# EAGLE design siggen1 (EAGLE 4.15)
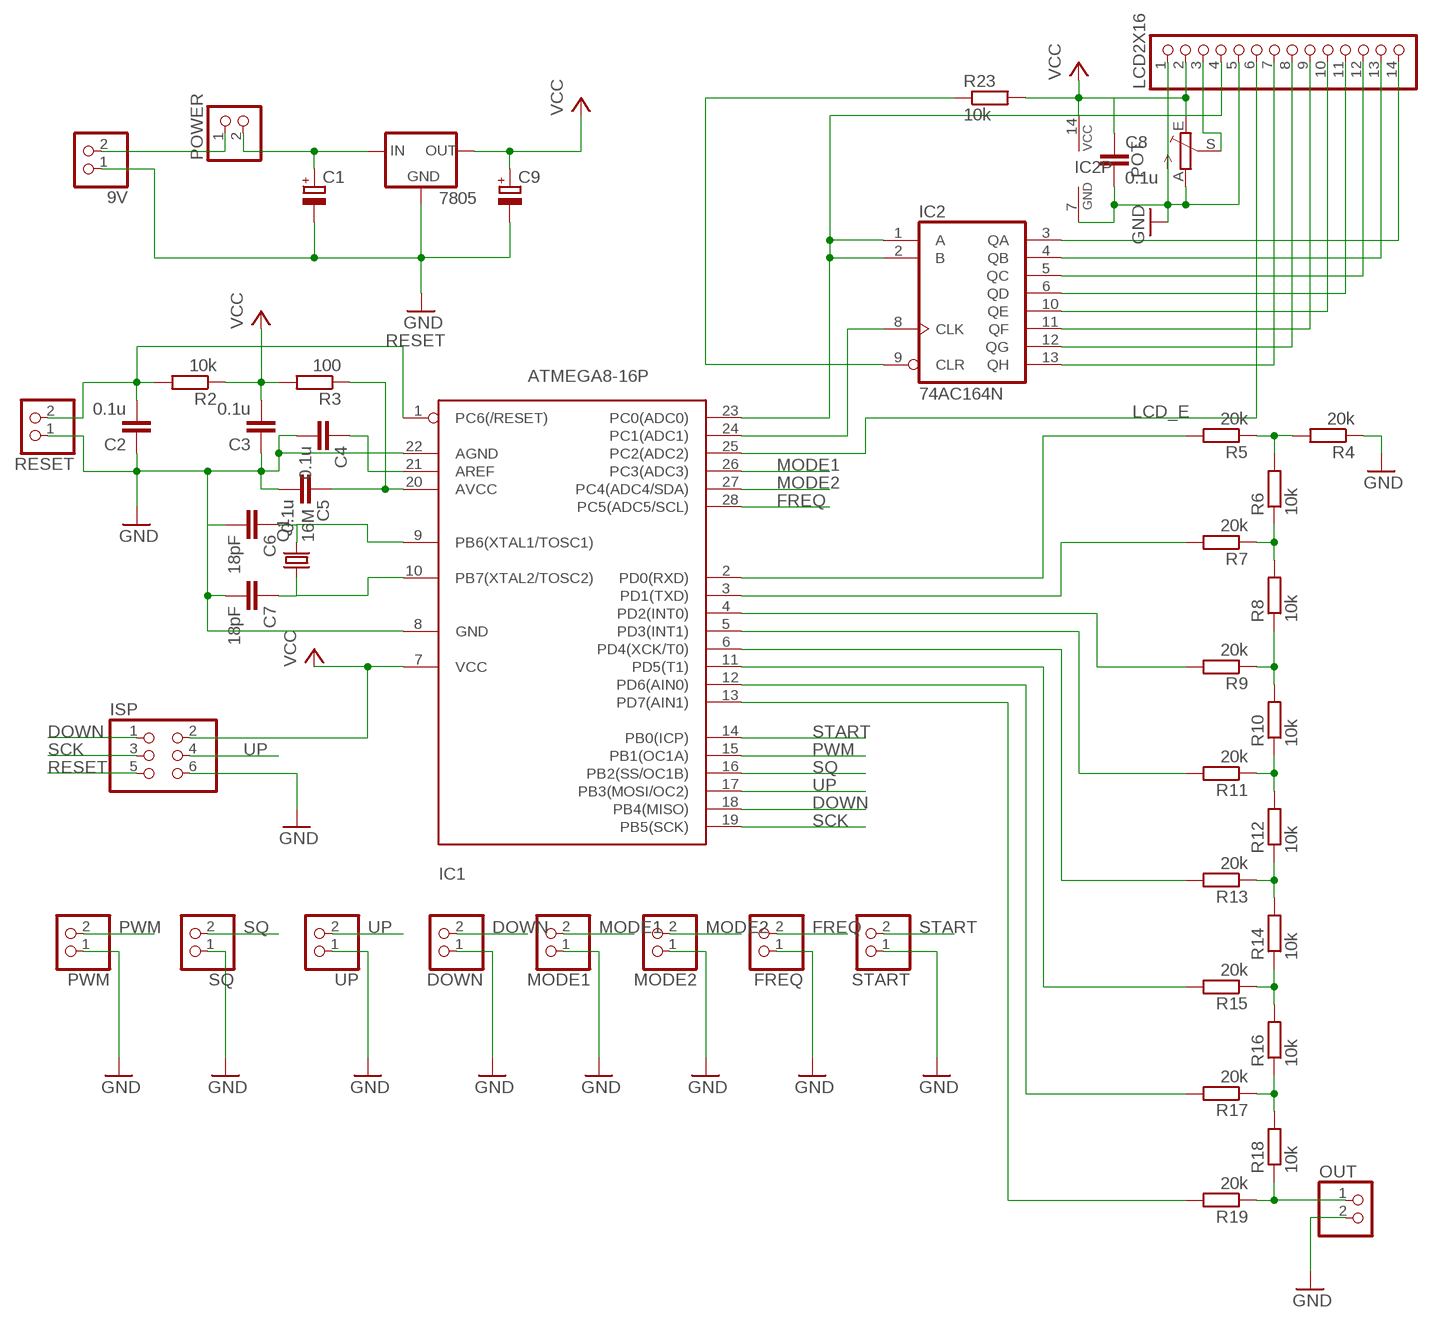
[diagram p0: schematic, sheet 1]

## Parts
9V  PINHD-1X2  [1X02]
7805  78MXXL  [78MXXL]
C1  CPOL-EUE5-4  [E5-4]
C2  0.1u  C-EUC0805  [C0805]
C3  0.1u  C-EUC0805  [C0805]
C4  0.1u  C-EUC0805  [C0805]
C5  0.1u  C-EUC0805  [C0805]
C6  18pF  C-EUC0805  [C0805]
C7  18pF  C-EUC0805  [C0805]
C8  0.1u  C-EUC0805  [C0805]
C9  CPOL-EUE5-4  [E5-4]
DOWN  PINHD-1X2  [1X02]
FREQ  PINHD-1X2  [1X02]
IC1  ATMEGA8-16P  [DIL28-3]
IC2  74AC164N  [DIL14]
ISP  PINHD-2X3  [2X03]
LCD2X16  PINHD-1X14  [1X14]
MODE1  PINHD-1X2  [1X02]
MODE2  PINHD-1X2  [1X02]
OUT  PINHD-1X2  [1X02]
POT  TRIM_EU-B64W  [B64W]
POWER  PINHD-1X2  [1X02]
PWM  PINHD-1X2  [1X02]
Q1  16M  CRYTALHC49S  [HC49/S]
R2  10k  R-EU_V526-0  [V526-0]
R3  100  R-EU_M0805  [M0805]
R4  20k  R-EU_M0805  [M0805]
R5  20k  R-EU_M0805  [M0805]
R6  10k  R-EU_M0805  [M0805]
R7  20k  R-EU_M0805  [M0805]
R8  10k  R-EU_M0805  [M0805]
R9  20k  R-EU_M0805  [M0805]
R10  10k  R-EU_M0805  [M0805]
R11  20k  R-EU_M0805  [M0805]
R12  10k  R-EU_M0805  [M0805]
R13  20k  R-EU_M0805  [M0805]
R14  10k  R-EU_M0805  [M0805]
R15  20k  R-EU_M0805  [M0805]
R16  10k  R-EU_M0805  [M0805]
R17  20k  R-EU_M0805  [M0805]
R18  10k  R-EU_M0805  [M0805]
R19  20k  R-EU_M0805  [M0805]
R23  10k  R-EU_M0805  [M0805]
RESET  PINHD-1X2  [1X02]
SQ  PINHD-1X2  [1X02]
START  PINHD-1X2  [1X02]
UP  PINHD-1X2  [1X02]

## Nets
DOWN: DOWN.2 IC1.18(PB4(MISO)) ISP.1
FREQ: FREQ.2 IC1.28(PC5(ADC5/SCL))
GND: 9V.1 7805.GND C1.- C2.1 C3.1 C4.2 C5.2 C6.2 C7.2 C8.2 C9.- DOWN.1 FREQ.1 IC1.8(GND) IC1.22(AGND) IC2.7(GND) ISP.6 LCD2X16.1 LCD2X16.5 MODE1.1 MODE2.1 OUT.2 POT.A PWM.1 R4.1 RESET.1 SQ.1 START.1 UP.1
LCD_E: IC1.25(PC2(ADC2)) LCD2X16.6
MODE1: IC1.26(PC3(ADC3)) MODE1.2
MODE2: IC1.27(PC4(ADC4/SDA)) MODE2.2
N$1: 7805.IN C1.+ POWER.2
N$2: C4.1 IC1.21(AREF)
N$3: C6.1 IC1.9(PB6(XTAL1/TOSC1)) Q1.2
N$4: C7.1 IC1.10(PB7(XTAL2/TOSC2)) Q1.1
N$5: LCD2X16.3 POT.S
N$6: IC2.3(QA) LCD2X16.14
N$7: IC2.4(QB) LCD2X16.13
N$8: IC2.5(QC) LCD2X16.12
N$9: C5.1 IC1.20(AVCC) R3.1
N$10: IC2.6(QD) LCD2X16.11
N$11: IC2.10(QE) LCD2X16.10
N$12: IC2.11(QF) LCD2X16.9
N$13: IC2.12(QG) LCD2X16.8
N$14: IC2.13(QH) LCD2X16.7
N$15: R4.2 R5.1 R6.2
N$16: IC2.9(CLR) R23.1
N$17: IC1.23(PC0(ADC0)) IC2.1(A) IC2.2(B) LCD2X16.4
N$18: R6.1 R7.1 R8.2
N$19: IC1.24(PC1(ADC1)) IC2.8(CLK)
N$20: R8.1 R9.1 R10.2
N$21: R10.1 R11.1 R12.2
N$22: R12.1 R13.1 R14.2
N$23: R14.1 R15.1 R16.2
N$24: R16.1 R17.1 R18.2
N$25: OUT.1 R18.1 R19.1
N$26: 9V.2 POWER.1
N$27: IC1.2(PD0(RXD)) R5.2
N$28: IC1.3(PD1(TXD)) R7.2
N$29: IC1.4(PD2(INT0)) R9.2
N$30: IC1.5(PD3(INT1)) R11.2
N$31: IC1.6(PD4(XCK/T0)) R13.2
N$32: IC1.11(PD5(T1)) R15.2
N$33: IC1.12(PD6(AIN0)) R17.2
N$34: IC1.13(PD7(AIN1)) R19.2
PWM: IC1.15(PB1(OC1A)) PWM.2
RESET: C2.2 IC1.1(PC6(/RESET)) ISP.5 R2.2 RESET.2
SCK: IC1.19(PB5(SCK)) ISP.3
SQ: IC1.16(PB2(SS/OC1B)) SQ.2
START: IC1.14(PB0(ICP)) START.2
UP: IC1.17(PB3(MOSI/OC2)) ISP.4 UP.2
VCC: 7805.OUT C3.2 C8.1 C9.+ IC1.7(VCC) IC2.14(VCC) ISP.2 LCD2X16.2 POT.E R2.1 R3.2 R23.2

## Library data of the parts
9V DOWN FREQ MODE1 MODE2 OUT POWER PWM RESET SQ START UP = pinhead:PINHD-1X2: PIN HEADER
7805 = v-reg:78MXXL: VOLTAGE REGULATOR
C1 C9 = rcl:CPOL-EU: POLARIZED CAPACITOR, European symbol
C2-C8 = rcl:C-EU: CAPACITOR, European symbol
IC1 = avr:ATMEGA8*P: MICROCONTROLLER 8 Kbytes FLASH 1 kbytes SRAM 512 bytes EEPROM USART 4-channel 10 bit ADC 2-channel 8 bit ADC
IC2 = 74xx-eu:74*164: 8-bit parallel out SHIFT REGISTER
ISP = pinhead:PINHD-2X3: PIN HEADER
LCD2X16 = pinhead:PINHD-1X14: PIN HEADER
POT = pot:TRIM_EU-: POTENTIOMETER
Q1 = crystal:CRYTAL: CRYSTAL
R2-R19 R23 = rcl:R-EU_: RESISTOR, European symbol

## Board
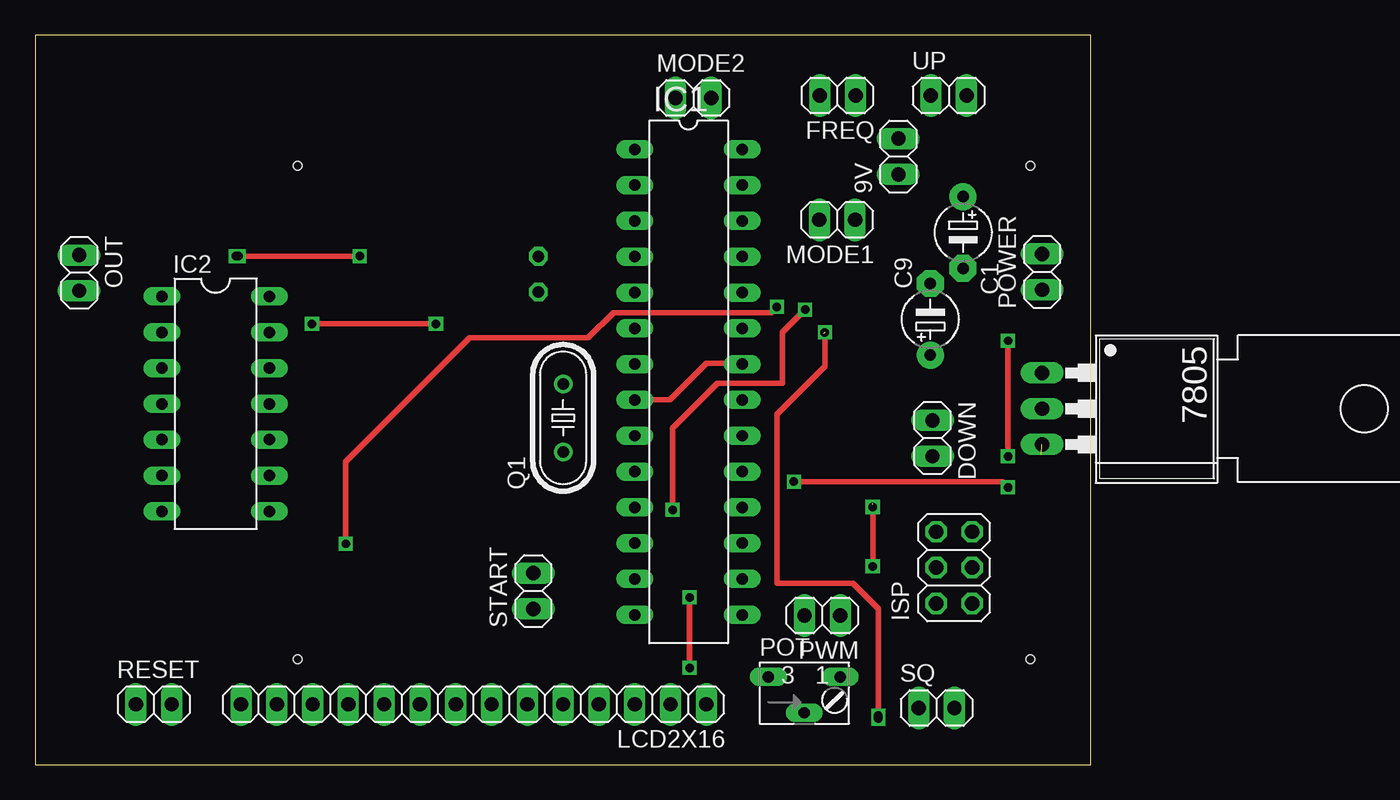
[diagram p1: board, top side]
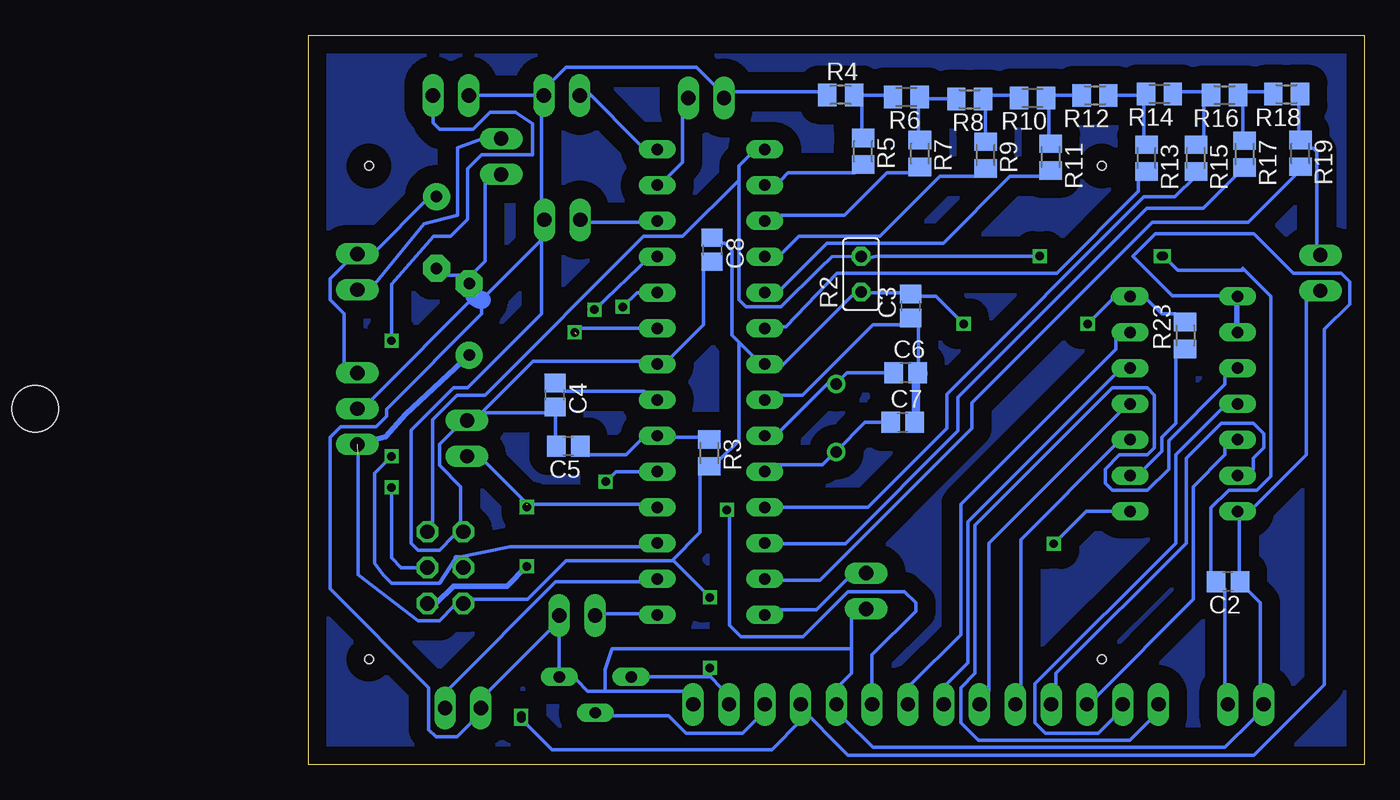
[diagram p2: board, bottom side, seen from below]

Size 74.91 x 51.74 mm. Coordinates in mm from the lower left corner, seen from the top.
Outline: 0,0 74.91,0 74.91,51.74 0,51.74 0,0
Copper layers (1*16): Top 0.035mm / dielectric 1.5mm / Bottom 0.035mm
Design rules "default": minimum track width 10mil, minimum drill 24mil, track to track 8mil, track to pad 8mil, pad to pad 8mil, via to via 8mil, smd to smd 8mil, copper to edge 40mil, drill to drill 8mil, minimum pad ring 10mil, minimum via ring 8mil, stop-mask expansion 4mil, vias tented up to drill 0mil, thermal gap 10mil
Holes 0.6 mm at 18.63,7.47 70.63,7.47 18.63,42.47 70.63,42.47

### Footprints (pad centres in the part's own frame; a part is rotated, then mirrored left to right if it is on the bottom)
1X02 = drill 1.016 long: 1 -1.27,0; 2 1.27,0
78MXXL = drill 1.016 long: GND 0,-5.08; IN -2.54,-5.08; OUT 2.54,-5.08 | hole 3.302: 0,17.78
E5-4 = drill 0.813 pad 1.905 round: + -2.54,0 | drill 0.813 pad 1.905 octagon: - 2.54,0
C0805 = smd 1.3 x 1.5: 1 -0.85,0; 2 0.85,0
DIL28-3 = drill 0.813 long: 1 -16.51,-3.81; 2 -13.97,-3.81; 3 -11.43,-3.81; 4 -8.89,-3.81; 5 -6.35,-3.81; 6 -3.81,-3.81; 7 -1.27,-3.81; 8 1.27,-3.81; 9 3.81,-3.81; 10 6.35,-3.81; 11 8.89,-3.81; 12 11.43,-3.81; 13 13.97,-3.81; 14 16.51,-3.81; 15 16.51,3.81; 16 13.97,3.81; 17 11.43,3.81; 18 8.89,3.81; 19 6.35,3.81; 20 3.81,3.81; 21 1.27,3.81; 22 -1.27,3.81; 23 -3.81,3.81; 24 -6.35,3.81; 25 -8.89,3.81; 26 -11.43,3.81; 27 -13.97,3.81; 28 -16.51,3.81
DIL14 = drill 0.813 long: 1 -7.62,-3.81; 2 -5.08,-3.81; 3 -2.54,-3.81; 4 0,-3.81; 5 2.54,-3.81; 6 5.08,-3.81; 7 7.62,-3.81; 8 7.62,3.81; 9 5.08,3.81; 10 2.54,3.81; 11 0,3.81; 12 -2.54,3.81; 13 -5.08,3.81; 14 -7.62,3.81
2X03 = drill 1.016 octagon: 1 -2.54,-1.27; 2 -2.54,1.27; 3 0,-1.27; 4 0,1.27; 5 2.54,-1.27; 6 2.54,1.27
1X14 = drill 1.016 long: 1 -16.51,0; 2 -13.97,0; 3 -11.43,0; 4 -8.89,0; 5 -6.35,0; 6 -3.81,0; 7 -1.27,0; 8 1.27,0; 9 3.81,0; 10 6.35,0; 11 8.89,0; 12 11.43,0; 13 13.97,0; 14 16.51,0
B64W = drill 0.813 long: A 2.54,0; E -2.54,0; S 0,-2.54
HC49/S = drill 0.813 round: 1 -2.413,0; 2 2.413,0
V526-0 = drill 0.813 octagon: 1 -1.27,0; 2 1.27,0
M0805 = smd 1.3 x 1.6: 1 -0.95,0; 2 0.95,0

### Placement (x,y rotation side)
9V  61.25,43.14 90 top
7805  76.53,25.25 270 top
C1  65.84,37.75 270 top
C2  9.67,12.98 180 bottom
C3  32.19,32.53 90 bottom
C4  57.43,26.22 270 bottom
C5  56.48,22.59 180 bottom
C6  32.55,27.8 0 bottom
C7  32.75,24.28 0 bottom
C8  46.28,36.52 270 bottom
C9  63.52,31.59 90 top
DOWN  63.67,23.15 270 top
FREQ  56.94,47.46 180 top
IC1  46.35,27.14 270 top
IC2  12.8,25.59 270 top
ISP  65.21,13.98 90 top
LCD2X16  31.11,4.28 180 top
MODE1  56.91,38.65 180 top
MODE2  46.7,47.29 0 top
OUT  3.12,34.88 270 top
POT  54.57,6.22 0 top
POWER  71.45,34.96 90 top
PWM  55.86,10.58 180 top
Q1  37.46,24.6 90 top
R2  35.71,34.79 90 bottom
R3  46.47,22.12 270 bottom
R4  37.15,47.51 0 bottom
R5  35.57,43.51 270 bottom
R6  32.5,47.37 180 bottom
R7  31.53,43.35 270 bottom
R8  27.99,47.21 180 bottom
R9  26.87,43.23 270 bottom
R10  23.53,47.3 180 bottom
R11  22.25,43.09 270 bottom
R12  19.11,47.48 180 bottom
R13  15.45,43.02 270 bottom
R14  14.53,47.58 180 bottom
R15  11.95,43.02 270 bottom
R16  9.91,47.5 180 bottom
R17  8.49,43.3 270 bottom
R18  5.5,47.56 180 bottom
R19  4.53,43.36 270 bottom
R23  12.7,30.44 90 bottom
RESET  8.41,4.28 0 top
SQ  63.96,4.02 0 top
START  35.34,12.32 90 top
UP  64.82,47.46 0 top

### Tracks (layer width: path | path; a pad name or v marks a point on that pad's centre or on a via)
DOWN  (via drill 0.6)  (1 unrouted)
  Top 0.406: v59.43,14.07 59.43,18.47
  Bottom 0.254: IC1.18 51.38,18.47 59.38,18.47 62.38,21.47 DOWN.2
  Bottom 0.406: ISP.1 65.86,11.44 64.63,12.67 60.83,12.67 v59.43,14.07
FREQ
  Bottom 0.254: IC1.28 51.38,43.97 55.13,47.72 FREQ.2
GND
  Top 0.406: IC1.8 45.03,25.87 47.63,28.47 50.23,28.47 IC1.22
  Bottom 0.254: R4.1 38.63,47.72 44.88,47.72 MODE2.1 46.13,48.22 47.38,49.47 56.63,49.47 57.63,48.47 FREQ.1 | FREQ.1 58.38,45.97 58.38,39.97 MODE1.1 58.38,37.22 | UP.1 62.88,47.47 58.88,47.47 FREQ.1 | C8.2 46.88,35.22 46.88,31.22 49.13,28.97 IC1.22 51.38,28.62 58.98,28.62 62.63,24.97 | C5.2 57.38,21.97 57.38,24.97 C4.2 58.13,24.97 62.63,24.97 | 62.63,24.97 DOWN.1 64.63,23.72 65.63,22.72 65.63,21.22 64.13,19.72 64.13,17.22 ISP.6 64.63,16.22 65.63,15.22 67.13,15.22 67.63,15.72 67.63,23.72 64.63,26.72 63.63,26.72 58.38,31.97 58.38,37.22 | OUT.2 4.13,32.97 4.13,21.97 7.88,18.22 IC2.7 8.88,17.47 8.88,13.72 C2.1 8.38,12.47 7.38,11.47 7.38,5.72 RESET.1 7.88,3.22 9.88,1.22 34.88,1.22 36.88,3.22 LCD2X16.5 37.13,5.72 36.38,6.47 36.38,8.22 | 53.88,5.22 55.13,5.22 55.88,5.97 POT.A 57.13,6.72 PWM.1 57.63,9.72 62.13,5.22 SQ.1 63.38,2.97 64.38,1.97 65.88,1.97 66.38,2.47 66.38,5.47 73.38,12.47 73.38,23.22 72.63,23.97 70.13,23.97 69.38,24.72 69.38,25.22 62.63,31.97 62.63,32.97 58.38,37.22 | 53.88,5.22 48.38,5.22 LCD2X16.1 | 36.38,8.22 36.38,10.47 START.1 | 32.88,31.22 34.88,31.22 39.88,26.22 41.38,26.22 IC1.8 | 32.88,31.22 C3.1 | 53.88,5.22 53.88,6.72 53.38,8.22 36.38,8.22 | 32.88,31.22 31.78,31.22 31.63,31.07 31.63,27.87 C6.2 | 7805.GND 70.38,25.97 63.13,33.22 C9.- | 9V.1 62.38,41.22 62.38,35.72 63.13,34.97 C9.- | C1.- 65.13,34.72 64.13,34.72 C9.-
  Bottom 0.61: C7.2 31.84,24.28 arc90 31.83,24.27 31.83,27.53 arc90 31.63,27.73
  Bottom 1.27: C6.2 arc90 31.63,27.73 | C9.- 63.49,34.13 arc90 63.23,33.87 63.23,33.57 arc-90 62.63,32.97
LCD_E  (via drill 0.6)
  Top 0.406: v45.23,18.07 45.23,23.87 48.43,27.07 53.03,27.07 53.03,30.67 v54.63,32.27
  Bottom 0.254: LCD2X16.6 34.92,7.78 31.83,10.87 31.83,11.47 32.63,12.27 36.63,12.27 39.83,9.07 44.23,9.07 45.03,9.87 45.03,17.87 v45.23,18.07 | IC1.25 50.67,36.03 v54.63,32.27
MODE1
  Bottom 0.254: IC1.26 51.38,38.47 54.88,38.47 MODE1.2
MODE2
  Bottom 0.254: IC1.27 49.38,41.72 48.38,42.72 48.38,45.97 MODE2.2
N$1
  Bottom 0.254: 7805.IN 72.38,28.47 72.38,31.97 73.38,32.97 73.38,34.47 72.38,35.47 POWER.2 70.13,36.47 66.63,39.97 C1.+
N$2
  Bottom 0.254: C4.1 56.88,26.47 51.13,26.47 IC1.21
N$3
  Bottom 0.254: IC1.9 41.38,23.72 37.88,27.22 Q1.2 37.46,27.04 36.7,27.8 C6.1
N$4
  Bottom 0.254: 41.58,21.14 IC1.10 | 41.58,21.14 41.38,21.22 | C7.1 35.42,24.28 37.46,22.24 Q1.1 37.51,22.19 38.43,21.27 41.63,21.27 41.58,21.22 41.58,21.14
N$5
  Bottom 0.254: POT.S 53.38,3.47 49.38,3.47 48.13,2.22 44.13,2.22 43.13,3.22 LCD2X16.3
N$6
  Bottom 0.254: IC2.3 9.88,27.47 9.88,26.97 13.88,22.97 13.88,20.97 15.38,19.47 17.88,19.47 18.38,19.97 18.38,20.97 17.38,21.97 15.38,21.97 14.88,22.47 14.88,26.22 15.38,26.72 17.88,26.72 27.63,16.97 27.63,6.47 28.63,5.47 28.63,2.97 27.38,1.72 16.63,1.72 15.13,3.22 LCD2X16.14
N$7
  Bottom 0.254: IC2.4 10.13,25.22 13.38,21.97 13.38,15.72 23.38,5.72 23.38,2.97 22.63,2.22 18.88,2.22 17.88,3.22 LCD2X16.13
N$8
  Bottom 0.254: IC2.5 9.88,22.47 9.88,21.97 12.13,19.72 12.13,11.72 19.13,4.72 LCD2X16.12
N$9
  Bottom 0.254: C5.1 55.13,21.97 52.38,21.97 51.38,22.97 IC1.20 48.88,23.22 47.13,23.22 R3.1
N$10
  Bottom 0.254: IC2.6 7.88,20.97 7.88,21.72 7.13,22.47 7.13,23.47 7.88,24.22 10.13,24.22 12.63,21.72 12.63,15.72 21.88,6.47 21.88,5.72 LCD2X16.11
N$11
  Bottom 0.254: IC2.10 17.63,22.72 24.38,15.97 24.38,5.72 LCD2X16.10
N$12
  Bottom 0.254: IC2.11 17.38,24.97 26.63,15.72 26.63,5.22 LCD2X16.9
N$13
  Bottom 0.254: IC2.12 17.63,27.72 28.13,17.22 28.13,7.22 29.63,5.72 LCD2X16.8
N$14
  Bottom 0.254: IC2.13 17.63,30.22 17.63,29.47 28.63,18.47 28.63,9.22 32.13,5.72 LCD2X16.7
N$15
  Bottom 0.254: R6.2 33.88,47.47 35.63,47.47 R4.2 35.63,46.72 35.63,44.97 R5.1
N$16
  Bottom 0.254: R23.1 13.38,28.97 13.38,24.22 14.38,23.22 14.38,22.22 15.63,20.97 IC2.9
N$17  (via drill 0.6)  (1 unrouted)
  Top 0.406: v59.83,3.27 59.83,11.07 58.03,12.87 52.63,12.87 52.63,24.87 56.03,28.27 56.03,30.67
  Bottom 0.254: IC2.1 9.13,32.72 9.13,31.22 IC2.2 8.99,33.03 9.23,33.27 13.63,33.27 16.43,36.07 14.83,37.67 7.83,37.67 5.03,34.87 1.63,34.87 1.03,34.27 1.03,32.67 2.83,30.87 2.83,5.67 7.83,0.67 36.63,0.67 40.23,4.27 40.22,4.28 LCD2X16.4 40,3.1 42.03,1.07 57.63,1.07 v59.83,3.27 | IC1.23 55.55,30.95 56.03,30.47
N$18
  Bottom 0.254: R8.2 29.38,47.22 31.13,47.22 R6.1 31.63,46.72 31.63,44.72 R7.1
N$19  (via drill 0.6)
  Top 0.406: v22.03,15.67 22.03,21.47 30.83,30.27 39.23,30.27 41.03,32.07 52.23,32.07 v52.63,32.47 | 50.23,33.47 50.21,33.49 IC1.24
  Bottom 0.254: IC2.8 19.73,17.97 v22.03,15.67 | IC1.24 51.61,33.49 v52.63,32.47
N$20
  Bottom 0.254: R9.1 26.88,44.72 26.88,46.47 R8.1 26.63,47.47 24.88,47.47 R10.2
N$21
  Bottom 0.254: R11.1 22.38,44.47 22.38,46.72 R10.1 22.13,47.47 20.63,47.47 R12.2
N$22
  Bottom 0.254: R13.1 15.63,44.47 15.63,46.97 R14.2 15.88,47.47 17.63,47.47 R12.1
N$23
  Bottom 0.254: R14.1 13.13,47.72 11.38,47.72 R16.2 11.38,46.72 11.38,44.47 R15.1
N$24
  Bottom 0.254: R17.1 8.63,44.72 8.63,46.72 R16.1 8.38,47.72 6.88,47.72 R18.2
N$25
  Bottom 0.254: R18.1 4.63,46.97 4.63,44.72 R19.1 3.88,43.72 3.63,43.72 3.38,43.47 3.38,36.72 OUT.1
N$26
  Bottom 0.254: POWER.1 70.61,33.69 70.23,34.07 66.73,38.37 64.33,38.97 64.33,43.77 62.78,44.32 9V.2
N$27
  Bottom 0.254: R5.2 36.13,41.97 40.88,41.97 41.38,41.47 IC1.2
N$28
  Bottom 0.254: R7.2 32.13,41.97 33.88,41.97 36.88,38.97 41.38,38.97 IC1.3
N$29
  Bottom 0.254: R9.2 27.63,41.72 30.13,41.72 34.38,37.47 40.13,37.47 41.38,36.22 IC1.4
N$30
  Bottom 0.254: R11.2 22.88,41.72 25.13,41.72 29.88,36.97 38.13,36.97 41.38,33.72 IC1.5
N$31
  Bottom 0.254: 16.03,42.07 16.03,40.67 21.83,34.87 37.43,34.87 41.03,31.07 42.23,31.07 42.43,30.87 42.51,30.95 IC1.6
  Bottom 0.305: 15.73,42.07 16.03,42.07
  Bottom 0.406: R13.2 15.73,42.07
N$32
  Bottom 0.254: R15.2 11.95,41.75 13.43,40.27 15.63,40.27 29.63,26.27 29.63,23.87 35.23,18.27 42.23,18.27 42.43,18.07 42.54,18.18 IC1.11
N$33
  Bottom 0.254: R17.2 8.55,42.35 11.43,39.47 15.43,39.47 28.83,26.07 28.83,23.67 36.83,15.67 42.63,15.67 42.59,15.71 IC1.12
N$34
  Bottom 0.254: R19.2 4.53,42.17 8.23,38.47 15.03,38.47 27.83,25.67 27.83,23.87 38.63,13.07 42.63,13.07 IC1.13
N$35  (via drill 0.6)
  other vias: 14.43,36.07
N$36  (via drill 0.6)
  other vias: 59.83,3.47
N$37  (via drill 0.6)
  other vias: 56.03,30.67
N$38
  pour Bottom (isolate 1.27, no thermals): 0.43,51.47 73.16,51.47 arc-90 74.43,50.2 74.43,0.67 1.7,0.67 arc-90 0.43,1.94
N$39  (via drill 0.6)
  other vias: 59.43,18.27
PWM
  Bottom 0.254: IC1.15 51.38,10.72 53.88,10.72 PWM.2
RESET  (via drill 0.6)
  Top 0.406: v14.23,36.07 v23.03,36.07
  Bottom 0.254: RESET.2 9.88,5.72 9.88,12.47 C2.2 10.88,13.72 10.88,18.22 9.63,19.47 7.63,19.47 6.63,20.47 6.63,33.22 8.63,35.22 8.63,35.07 13.23,35.07 v14.23,36.07 | 44.38,41.47 44.38,42.47 43.63,43.22 IC1.1 | 44.38,41.47 44.38,32.97 43.88,32.47 41.38,32.47 38.63,35.22 37.78,36.02 R2.2 35.33,36.02 35.13,35.97 34.63,36.07 v23.03,36.07 | 44.38,41.47 48.38,37.47 51.13,37.47 62.38,26.22 64.38,26.22 66.13,24.47 66.13,17.22 ISP.5
SCK  (via drill 0.6)
  Top 0.406: v53.83,20.07 68.63,20.07 v69.03,19.67
  Bottom 0.254: ISP.3 68.34,13.98 69.03,14.67 v69.03,19.67 | IC1.19 53.11,20.79 v53.83,20.07
SQ
  Bottom 0.254: IC1.16 51.38,12.97 57.38,12.97 64.88,5.47 SQ.2
START
  Bottom 0.254: IC1.14 41.38,10.97 38.88,10.97 36.63,13.22 START.2
UP  (via drill 0.6)
  Top 0.406: v69.03,21.87 v69.03,30.07
  Bottom 0.254: IC1.17 51.38,15.47 60.63,15.47 64.43,14.67 65.63,12.87 69.03,12.87 69.63,13.47 70.23,14.27 70.23,20.67 v69.03,21.87 | UP.2 66.09,45.53 65.63,45.07 63.23,45.07 62.03,46.27 60.23,46.27 59.03,45.47 59.03,43.27 62.63,43.27 63.63,42.27 63.63,38.67 64.83,37.47 66.03,37.47 69.03,34.07 v69.03,30.07
  Bottom 0.406: ISP.4 63.83,13.98 63.83,14.67 64.43,14.67
VCC  (via drill 0.6)  (1 unrouted)
  Top 0.406: 46.43,12.07 v46.43,11.87 v46.43,6.87 | v19.63,31.27 v28.43,31.27
  Bottom 0.254: 71.38,21.97 71.38,13.47 67.13,10.22 65.63,10.22 64.63,11.22 ISP.2 63.38,11.72 59.38,11.72 56.63,14.47 49.13,14.47 | R23.2 13.38,31.97 14.38,31.97 15.38,32.97 IC2.14 17.88,33.22 17.88,33.02 v19.63,31.27 | 44.38,29.97 43.38,28.97 IC1.7 41.38,28.22 36.38,33.22 R2.1 35.13,33.47 32.88,33.47 C3.2 31.63,33.22 30.38,33.22 v28.43,31.27 | 44.38,29.97 44.88,30.47 44.88,36.47 45.38,36.97 45.63,36.97 C8.1 | 44.38,29.97 44.38,22.97 45.63,21.72 45.88,21.72 R3.2 47.13,20.72 47.13,16.47 49.13,14.47 | 46.38,6.22 45.63,5.47 LCD2X16.2 | 46.38,6.22 POT.E | 49.13,14.47 49.03,14.47 v46.43,11.87 | 46.38,6.22 46.38,6.82 v46.43,6.87
  Bottom 0.406: C9.+ 68.03,24.87 69.43,23.27 71.63,22.67 7805.OUT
